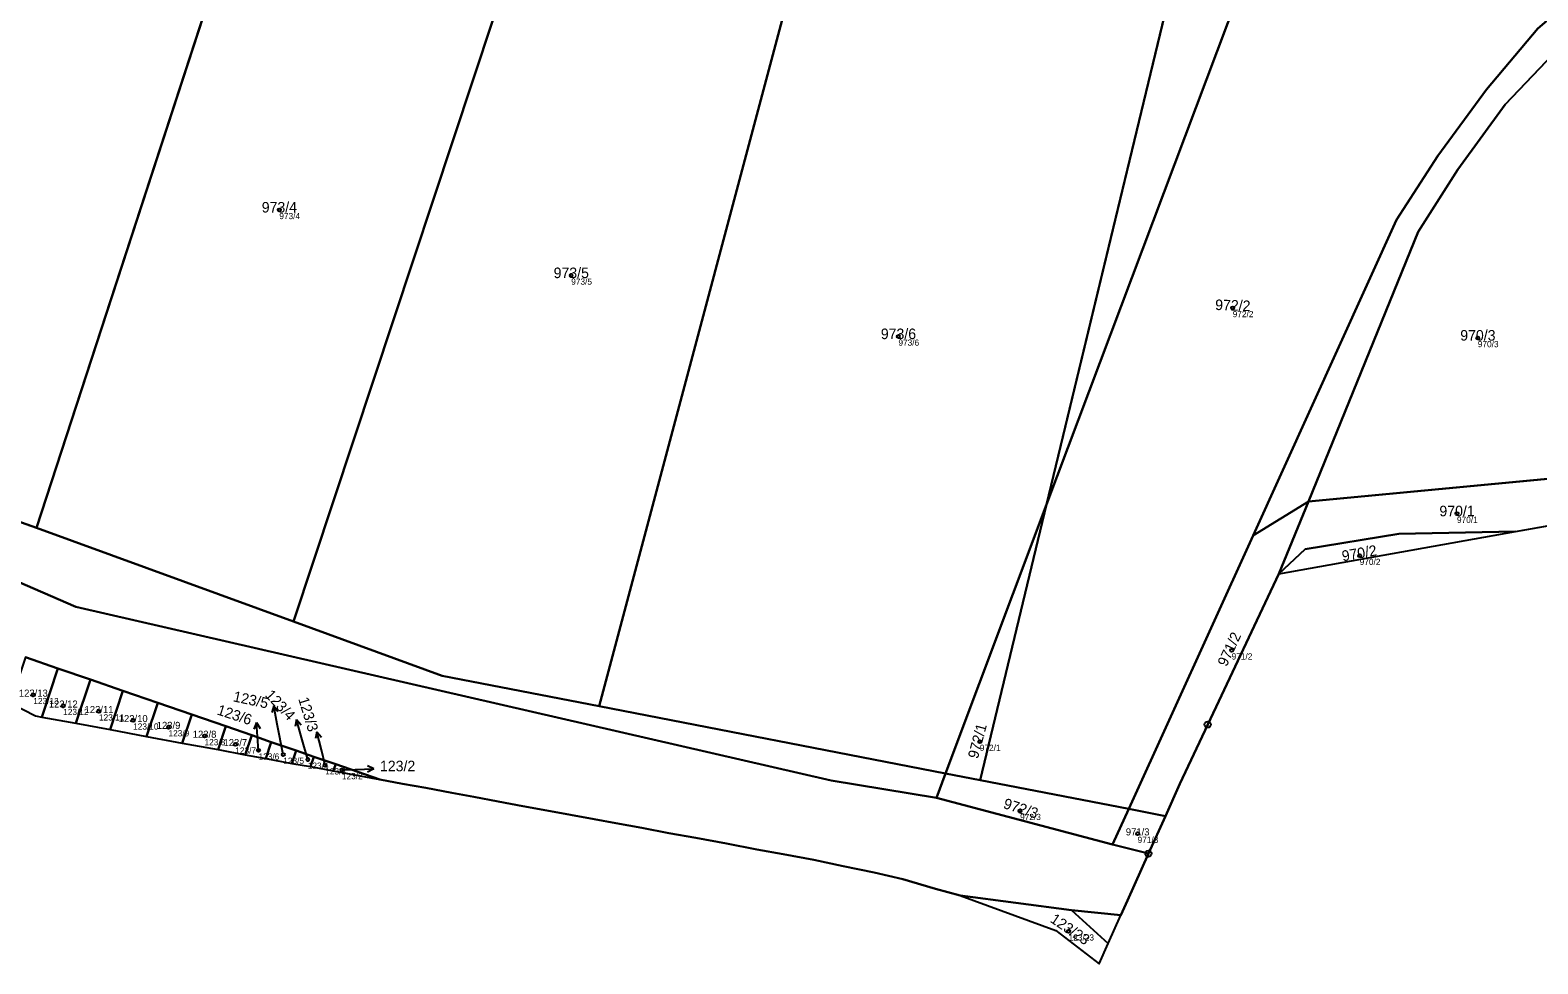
# Model space of a CAD drawing. Extents: x -603967 to -594699, y -1179315 to -1165625.
# Drawn here: x -597028 to -596784.9, y -1173029 to -1172878.5 of the extents above; entities that cross this region are included whole.
import ezdxf

# ---------------------------------------------------------------- set-up
doc = ezdxf.new("R2010")
doc.units = 0
for name, color, linetype in [('Definiční body', 7, 'Continuous'), ('Hranice parcel', 7, 'Continuous'), ('Parcelní čísla', 7, 'Continuous'), ('Polygon ku', 7, 'Continuous'), ('Polygon parcely', 7, 'Continuous'), ('Pop  PČ popisy', 7, 'Continuous'), ('Vnitřní kresba', 7, 'Continuous'), ('Značky bodu BP', 7, 'Continuous')]:
    doc.layers.add(name, color=color, linetype=linetype)

msp = doc.modelspace()

# ---------------------------------------------------------------- linework, layer by layer
at = {"layer": 'Definiční body'}
for centre in [(-596987.8, -1172907.46994), (-596940.73, -1172918.03994), (-596834.07, -1172923.26994), (-596887.97, -1172927.86994), (-596794.54, -1172928.10994), (-596797.9, -1172956.42994), (-596813.59, -1172963.20994), (-596834.24, -1172978.44994), (-597027.47, -1172985.63994), (-597022.65, -1172987.39994), (-597016.88, -1172988.27994), (-597011.37, -1172989.74994), (-597005.67, -1172990.83994), (-596999.86, -1172992.26994), (-596994.9, -1172993.61994), (-596874.84, -1172993.17994), (-596991.15, -1172994.58994), (-596987.16, -1172995.25994), (-596983.21, -1172996.05994), (-596980.4, -1172996.97994), (-596977.7, -1172997.73994), (-596868.35, -1173004.32994), (-596849.4, -1173008.00994), (-596860.52, -1173023.74994)]:
    msp.add_circle(centre, 0.25, dxfattribs=at)
at = {"layer": 'Hranice parcel'}
for p, q in [((-596822.8, -1172845.29), (-596864.07, -1172954.95)), ((-597026.93, -1172958.74), (-596990.34, -1172846.48)), ((-596985.54, -1172973.81), (-596943.64, -1172847.49)), ((-596936.25, -1172987.46), (-596898.99, -1172847.77)), ((-596864.07, -1172954.95), (-596837.74, -1172845.87)), ((-597073.38, -1172942.23), (-597026.93, -1172958.74)), ((-597075.1, -1172947.81), (-597020.63, -1172971.43)), ((-596770.73, -1172949.64), (-596821.84, -1172954.45)), ((-596830.78, -1172959.97), (-596821.84, -1172954.45)), ((-596821.84, -1172954.45), (-596826.61, -1172966.14)), ((-596864.07, -1172954.95), (-596880.38, -1172998.29)), ((-596874.79, -1172999.37), (-596864.07, -1172954.95)), ((-596788.47, -1172959.3), (-596769.76, -1172956)), ((-597026.93, -1172958.74), (-596985.54, -1172973.81)), ((-596826.61, -1172966.14), (-596788.47, -1172959.3)), ((-596830.78, -1172959.97), (-596850.82, -1173004.02)), ((-596826.61, -1172966.14), (-596838.09, -1172990.42)), ((-597028.74, -1172979.56), (-597023.49, -1172981.37)), ((-597023.49, -1172981.37), (-597026.09, -1172989.23)), ((-597023.49, -1172981.37), (-597018.25, -1172983.18)), ((-597018.25, -1172983.18), (-597020.6, -1172990.18)), ((-597018.25, -1172983.18), (-597013.02, -1172984.99)), ((-597013.02, -1172984.99), (-597015.06, -1172991.24)), ((-597013.02, -1172984.99), (-597007.4, -1172986.93)), ((-597007.4, -1172986.93), (-597009.2, -1172992.34)), ((-597007.4, -1172986.93), (-597001.92, -1172988.82)), ((-597001.92, -1172988.82), (-597003.44, -1172993.41)), ((-597001.92, -1172988.82), (-596996.45, -1172990.7)), ((-596936.25, -1172987.46), (-596880.38, -1172998.29)), ((-597026.09, -1172989.23), (-597020.6, -1172990.18)), ((-597020.6, -1172990.18), (-597015.06, -1172991.24)), ((-597015.06, -1172991.24), (-597009.2, -1172992.34)), ((-596996.45, -1172990.7), (-596997.67, -1172994.45)), ((-596996.45, -1172990.7), (-596992.25, -1172992.15)), ((-596838.09, -1172990.42), (-596842.61, -1173000)), ((-597009.2, -1172992.34), (-597003.44, -1172993.41)), ((-597003.44, -1172993.41), (-596997.67, -1172994.45)), ((-596992.25, -1172992.15), (-596993.31, -1172995.28)), ((-596992.25, -1172992.15), (-596989.1, -1172993.24)), ((-596989.1, -1172993.24), (-596990, -1172995.9)), ((-596989.1, -1172993.24), (-596985.08, -1172994.62)), ((-596997.67, -1172994.45), (-596993.31, -1172995.28)), ((-596993.31, -1172995.28), (-596990, -1172995.9)), ((-596990, -1172995.9), (-596985.77, -1172996.68)), ((-596985.08, -1172994.62), (-596985.77, -1172996.68)), ((-596985.08, -1172994.62), (-596982.23, -1172995.61)), ((-596982.23, -1172995.61), (-596982.77, -1172997.21)), ((-596982.23, -1172995.61), (-596978.71, -1172996.82)), ((-596985.77, -1172996.68), (-596982.77, -1172997.21)), ((-596982.77, -1172997.21), (-596979.1, -1172997.9)), ((-596978.71, -1172996.82), (-596979.1, -1172997.9)), ((-596979.1, -1172997.9), (-596971.59, -1172999.28)), ((-596978.71, -1172996.82), (-596971.59, -1172999.28)), ((-596880.38, -1172998.29), (-596881.85, -1173002.21)), ((-596880.38, -1172998.29), (-596874.79, -1172999.37)), ((-596967.93, -1172999.96), (-596971.59, -1172999.28)), ((-596964.19, -1173000.64), (-596967.93, -1172999.96)), ((-596959.97, -1173001.43), (-596964.19, -1173000.64)), ((-596874.79, -1172999.37), (-596850.82, -1173004.02)), ((-596842.61, -1173000), (-596844.91, -1173005.17)), ((-596956.44, -1173002.09), (-596959.97, -1173001.43)), ((-596952.52, -1173002.81), (-596956.44, -1173002.09)), ((-596948.52, -1173003.55), (-596952.52, -1173002.81)), ((-596881.85, -1173002.21), (-596853.43, -1173009.77)), ((-596944.65, -1173004.27), (-596948.52, -1173003.55)), ((-596940.84, -1173004.97), (-596944.65, -1173004.27)), ((-596937.01, -1173005.68), (-596940.84, -1173004.97)), ((-596933.51, -1173006.33), (-596937.01, -1173005.68)), ((-596850.82, -1173004.02), (-596853.43, -1173009.77)), ((-596850.82, -1173004.02), (-596844.91, -1173005.17)), ((-596844.91, -1173005.17), (-596847.65, -1173011.23)), ((-596929.34, -1173007.09), (-596933.51, -1173006.33)), ((-596924.98, -1173007.91), (-596929.34, -1173007.09)), ((-596920.63, -1173008.7), (-596924.98, -1173007.91)), ((-596915.7, -1173009.6), (-596920.63, -1173008.7)), ((-596910.8, -1173010.54), (-596915.7, -1173009.6)), ((-596906.56, -1173011.3), (-596910.8, -1173010.54)), ((-596853.43, -1173009.77), (-596847.65, -1173011.23)), ((-596901.61, -1173012.25), (-596906.56, -1173011.3)), ((-596896.86, -1173013.25), (-596901.61, -1173012.25)), ((-596891.86, -1173014.28), (-596896.86, -1173013.25)), ((-596887.26, -1173015.33), (-596891.86, -1173014.28)), ((-596881.97, -1173016.88), (-596887.26, -1173015.33)), ((-596878.01, -1173017.99), (-596881.97, -1173016.88)), ((-596878.01, -1173017.99), (-596862.6, -1173023.61)), ((-596862.6, -1173023.61), (-596855.6, -1173028.99))]:
    msp.add_line(p, q, dxfattribs=at)
for points in [[(-596748.76, -1172839.35), (-596749.31, -1172846.64), (-596755.77, -1172857.84), (-596763.88, -1172864.57), (-596772.39, -1172868.75), (-596779.67, -1172873.77), (-596784.84, -1172878.21), (-596793.12, -1172888.04), (-596800.99, -1172898.76), (-596807.63, -1172909.06), (-596830.78, -1172959.97)], [(-596781.25, -1172881.18), (-596790.11, -1172890.5), (-596797.77, -1172900.95), (-596804.18, -1172910.98), (-596821.84, -1172954.45)], [(-596826.61, -1172966.14), (-596822.38, -1172962.16), (-596807.27, -1172959.66), (-596788.47, -1172959.3)], [(-597020.63, -1172971.43), (-596898.81, -1172999.45), (-596881.85, -1173002.21)], [(-596985.54, -1172973.81), (-596961.56, -1172982.55), (-596936.25, -1172987.46)], [(-597031.2, -1172986.91), (-597027.13, -1172988.99), (-597026.09, -1172989.23)], [(-596847.65, -1173011.23), (-596851.03, -1173018.78), (-596852.09, -1173021.17)], [(-596852.09, -1173021.17), (-596860.07, -1173020.33), (-596878.01, -1173017.99)], [(-596855.6, -1173028.99), (-596854.12, -1173025.71), (-596852.09, -1173021.17)]]:
    msp.add_lwpolyline(points, dxfattribs=at)
at = {"layer": 'Polygon ku'}
msp.add_lwpolyline([(-597031.2, -1172986.91), (-597027.13, -1172988.99), (-597026.09, -1172989.23), (-597020.6, -1172990.18), (-597015.06, -1172991.24), (-597009.2, -1172992.34), (-597003.44, -1172993.41), (-596997.67, -1172994.45), (-596993.31, -1172995.28), (-596990, -1172995.9), (-596985.77, -1172996.68), (-596982.77, -1172997.21), (-596979.1, -1172997.9), (-596971.59, -1172999.28), (-596967.93, -1172999.96), (-596964.19, -1173000.64), (-596959.97, -1173001.43), (-596956.44, -1173002.09), (-596952.52, -1173002.81), (-596948.52, -1173003.55), (-596944.65, -1173004.27), (-596940.84, -1173004.97), (-596937.01, -1173005.68), (-596933.51, -1173006.33), (-596929.34, -1173007.09), (-596924.98, -1173007.91), (-596920.63, -1173008.7), (-596915.7, -1173009.6), (-596910.8, -1173010.54), (-596906.56, -1173011.3), (-596901.61, -1173012.25), (-596896.86, -1173013.25), (-596891.86, -1173014.28), (-596887.26, -1173015.33), (-596881.97, -1173016.88), (-596878.01, -1173017.99), (-596862.6, -1173023.61), (-596855.6, -1173028.99), (-596854.12, -1173025.71), (-596852.09, -1173021.17), (-596851.03, -1173018.78), (-596847.65, -1173011.23), (-596844.91, -1173005.17), (-596842.61, -1173000), (-596838.09, -1172990.42), (-596826.61, -1172966.14), (-596788.47, -1172959.3), (-596769.76, -1172956)], dxfattribs=at)
at = {"layer": 'Polygon parcely'}
for points in [[(-596784.84, -1172878.21), (-596793.12, -1172888.04), (-596800.99, -1172898.76), (-596807.63, -1172909.06), (-596830.78, -1172959.97), (-596821.84, -1172954.45), (-596804.18, -1172910.98), (-596797.77, -1172900.95), (-596790.11, -1172890.5), (-596781.25, -1172881.18), (-596776.38, -1172876.94), (-596770.13, -1172873.12), (-596762.46, -1172870.6), (-596752.18, -1172869.36), (-596749.45, -1172866.51), (-596739.86, -1172838.12), (-596743.8, -1172838.67), (-596747.11, -1172839.12), (-596748.76, -1172839.35), (-596749.31, -1172846.64), (-596755.77, -1172857.84), (-596763.88, -1172864.57), (-596772.39, -1172868.75), (-596779.67, -1172873.77)], [(-596864.07, -1172954.95), (-596874.79, -1172999.37), (-596850.82, -1173004.02), (-596830.78, -1172959.97), (-596807.63, -1172909.06), (-596800.99, -1172898.76), (-596793.12, -1172888.04), (-596784.84, -1172878.21), (-596779.67, -1172873.77), (-596772.39, -1172868.75), (-596763.88, -1172864.57), (-596755.77, -1172857.84), (-596749.31, -1172846.64), (-596748.76, -1172839.35), (-596761.98, -1172839.62), (-596770.71, -1172839.61), (-596781.48, -1172840.52), (-596791.83, -1172841.5), (-596822.8, -1172845.29)], [(-596822.8, -1172845.29), (-596837.74, -1172845.87), (-596864.07, -1172954.95)], [(-597026.93, -1172958.74), (-596990.34, -1172846.48), (-597014.79, -1172845.99), (-597021.38, -1172845.6), (-597028.12, -1172847.57), (-597034.3, -1172850.24), (-597040.39, -1172854.43), (-597045.25, -1172860.28), (-597049.04, -1172866.95), (-597052.36, -1172873.78), (-597073.38, -1172942.23)], [(-596985.54, -1172973.81), (-596943.64, -1172847.49), (-596944.87, -1172847.4), (-596990.34, -1172846.48), (-597026.93, -1172958.74)], [(-596961.56, -1172982.55), (-596936.25, -1172987.46), (-596898.99, -1172847.77), (-596900.96, -1172847.77), (-596926.4, -1172848.75), (-596943.64, -1172847.49), (-596985.54, -1172973.81)], [(-596880.38, -1172998.29), (-596864.07, -1172954.95), (-596837.74, -1172845.87), (-596841.19, -1172846.01), (-596888.63, -1172847.79), (-596898.99, -1172847.77), (-596936.25, -1172987.46)], [(-596797.77, -1172900.95), (-596804.18, -1172910.98), (-596821.84, -1172954.45), (-596770.73, -1172949.64), (-596781.25, -1172881.18), (-596790.11, -1172890.5)], [(-596898.81, -1172999.45), (-596881.85, -1173002.21), (-596880.38, -1172998.29), (-596936.25, -1172987.46), (-596961.56, -1172982.55), (-596985.54, -1172973.81), (-597026.93, -1172958.74), (-597073.38, -1172942.23), (-597075.1, -1172947.81), (-597020.63, -1172971.43)], [(-596826.61, -1172966.14), (-596822.38, -1172962.16), (-596807.27, -1172959.66), (-596788.47, -1172959.3), (-596769.76, -1172956), (-596770.73, -1172949.64), (-596821.84, -1172954.45)], [(-596844.91, -1173005.17), (-596842.61, -1173000), (-596838.09, -1172990.42), (-596826.61, -1172966.14), (-596821.84, -1172954.45), (-596830.78, -1172959.97), (-596850.82, -1173004.02)], [(-596874.79, -1172999.37), (-596864.07, -1172954.95), (-596880.38, -1172998.29)], [(-596788.47, -1172959.3), (-596807.27, -1172959.66), (-596822.38, -1172962.16), (-596826.61, -1172966.14)], [(-597031.2, -1172986.91), (-597027.13, -1172988.99), (-597026.09, -1172989.23), (-597023.49, -1172981.37), (-597028.74, -1172979.56)], [(-597026.09, -1172989.23), (-597020.6, -1172990.18), (-597018.25, -1172983.18), (-597023.49, -1172981.37)], [(-597020.6, -1172990.18), (-597015.06, -1172991.24), (-597013.02, -1172984.99), (-597018.25, -1172983.18)], [(-597015.06, -1172991.24), (-597009.2, -1172992.34), (-597007.4, -1172986.93), (-597013.02, -1172984.99)], [(-597007.4, -1172986.93), (-597009.2, -1172992.34), (-597003.44, -1172993.41), (-597001.92, -1172988.82)], [(-597003.44, -1172993.41), (-596997.67, -1172994.45), (-596996.45, -1172990.7), (-597001.92, -1172988.82)], [(-596997.67, -1172994.45), (-596993.31, -1172995.28), (-596992.25, -1172992.15), (-596996.45, -1172990.7)], [(-596993.31, -1172995.28), (-596990, -1172995.9), (-596989.1, -1172993.24), (-596992.25, -1172992.15)], [(-596990, -1172995.9), (-596985.77, -1172996.68), (-596985.08, -1172994.62), (-596989.1, -1172993.24)], [(-596985.77, -1172996.68), (-596982.77, -1172997.21), (-596982.23, -1172995.61), (-596985.08, -1172994.62)], [(-596982.77, -1172997.21), (-596979.1, -1172997.9), (-596978.71, -1172996.82), (-596982.23, -1172995.61)], [(-596979.1, -1172997.9), (-596971.59, -1172999.28), (-596978.71, -1172996.82)], [(-596853.43, -1173009.77), (-596850.82, -1173004.02), (-596874.79, -1172999.37), (-596880.38, -1172998.29), (-596881.85, -1173002.21)], [(-596847.65, -1173011.23), (-596844.91, -1173005.17), (-596850.82, -1173004.02), (-596853.43, -1173009.77)], [(-596852.09, -1173021.17), (-596860.07, -1173020.33), (-596878.01, -1173017.99), (-596862.6, -1173023.61), (-596855.6, -1173028.99), (-596854.12, -1173025.71)]]:
    msp.add_lwpolyline(points, close=True, dxfattribs=at)
msp.add_lwpolyline([(-597028.74, -1172979.56), (-597023.49, -1172981.37), (-597018.25, -1172983.18), (-597013.02, -1172984.99), (-597007.4, -1172986.93), (-597001.92, -1172988.82), (-596996.45, -1172990.7), (-596992.25, -1172992.15), (-596989.1, -1172993.24), (-596985.08, -1172994.62), (-596982.23, -1172995.61), (-596978.71, -1172996.82), (-596971.59, -1172999.28), (-596967.93, -1172999.96), (-596964.19, -1173000.64), (-596959.97, -1173001.43), (-596956.44, -1173002.09), (-596952.52, -1173002.81), (-596948.52, -1173003.55), (-596944.65, -1173004.27), (-596940.84, -1173004.97), (-596937.01, -1173005.68), (-596933.51, -1173006.33), (-596929.34, -1173007.09), (-596924.98, -1173007.91), (-596920.63, -1173008.7), (-596915.7, -1173009.6), (-596910.8, -1173010.54), (-596906.56, -1173011.3), (-596901.61, -1173012.25), (-596896.86, -1173013.25), (-596891.86, -1173014.28), (-596887.26, -1173015.33), (-596881.97, -1173016.88), (-596878.01, -1173017.99), (-596860.07, -1173020.33), (-596852.09, -1173021.17), (-596851.03, -1173018.78), (-596847.65, -1173011.23), (-596853.43, -1173009.77), (-596881.85, -1173002.21), (-596898.81, -1172999.45), (-597020.63, -1172971.43), (-597075.1, -1172947.81)], dxfattribs=at)
at = {"layer": 'Pop  PČ popisy'}
for p, q in [((-596988.703, -1172987.424), (-596989.003, -1172988.503)), ((-596988.13, -1172990.37), (-596988.703, -1172987.424)), ((-596988.703, -1172987.424), (-596988.02, -1172988.312)), ((-596991.459, -1172990.116), (-596991.889, -1172991.15)), ((-596991.25, -1172993.11), (-596991.459, -1172990.116)), ((-596991.459, -1172990.116), (-596990.89, -1172991.08)), ((-596987.16, -1172995.26), (-596988.13, -1172990.37)), ((-596985.037, -1172989.625), (-596985.242, -1172990.726)), ((-596984.21, -1172992.51), (-596985.037, -1172989.625)), ((-596985.037, -1172989.625), (-596984.28, -1172990.45)), ((-596991.15, -1172994.59), (-596991.25, -1172993.11)), ((-596983.21, -1172996.06), (-596984.21, -1172992.51)), ((-596981.726, -1172991.598), (-596981.97, -1172992.691)), ((-596981, -1172994.51), (-596981.726, -1172991.598)), ((-596981.726, -1172991.598), (-596980.998, -1172992.449)), ((-596980.4, -1172996.98), (-596981, -1172994.51)), ((-596977.7, -1172997.74), (-596975.57, -1172997.65)), ((-596975.57, -1172997.65), (-596972.571, -1172997.545)), ((-596972.571, -1172997.545), (-596973.589, -1172997.08)), ((-596972.571, -1172997.545), (-596973.554, -1172998.081))]:
    msp.add_line(p, q, dxfattribs=at)
at = {"layer": 'Vnitřní kresba'}
msp.add_line((-596860.07, -1173020.33), (-596854.12, -1173025.71), dxfattribs=at)
at = {"layer": 'Značky bodu BP'}
for centre, radius in [((-596838.09, -1172990.41988), 0.5), ((-596838.09, -1172990.41988), 0.0303), ((-596847.65, -1173011.22988), 0.5), ((-596847.65, -1173011.22988), 0.0303)]:
    msp.add_circle(centre, radius, dxfattribs=at)

# ---------------------------------------------------------------- texts
at = {"layer": 'Definiční body'}
for s, p in [('973/4', (-596987.8, -1172908.959)), ('973/5', (-596940.73, -1172919.529)), ('972/2', (-596834.07, -1172924.759)), ('973/6', (-596887.97, -1172929.359)), ('970/3', (-596794.54, -1172929.599)), ('970/1', (-596797.9, -1172957.919)), ('970/2', (-596813.59, -1172964.699)), ('971/2', (-596834.24, -1172979.939)), ('123/13', (-597027.47, -1172987.129)), ('123/12', (-597022.65, -1172988.889)), ('123/11', (-597016.88, -1172989.769)), ('123/10', (-597011.37, -1172991.239)), ('123/9', (-597005.67, -1172992.329)), ('123/8', (-596999.86, -1172993.759)), ('972/1', (-596874.84, -1172994.669)), ('123/7', (-596994.9, -1172995.109)), ('123/6', (-596991.15, -1172996.079)), ('123/5', (-596987.16, -1172996.749)), ('123/4', (-596983.21, -1172997.549)), ('123/3', (-596980.4, -1172998.469)), ('123/2', (-596977.7, -1172999.229)), ('972/3', (-596868.35, -1173005.819)), ('971/3', (-596849.4, -1173009.499)), ('123/23', (-596860.52, -1173025.239))]:
    msp.add_text(s, height=0.999996, dxfattribs=at).set_placement(p)
at = {"layer": 'Parcelní čísla'}
for s, height, p in [('973/4', 1.699998, (-596990.636, -1172907.895)), ('973/5', 1.699998, (-596943.566, -1172918.465)), ('973/6', 1.699998, (-596890.806, -1172928.295)), ('970/3', 1.699998, (-596797.376, -1172928.535)), ('970/1', 1.699998, (-596800.736, -1172956.855)), ('123/13', 1.14, (-597029.794, -1172985.925)), ('123/12', 1.14, (-597024.974, -1172987.685)), ('123/11', 1.14, (-597019.204, -1172988.565)), ('123/10', 1.14, (-597013.694, -1172990.035)), ('123/9', 1.14, (-597007.571, -1172991.125)), ('123/8', 1.14, (-597001.761, -1172992.555)), ('123/7', 1.14, (-596996.801, -1172993.905)), ('123/2', 1.699998, (-596971.57, -1172997.955)), ('971/3', 1.14, (-596851.301, -1173008.295))]:
    msp.add_text(s, height=height, dxfattribs=at).set_placement(p)
for s, rotation, p in [('972/2', 358, (-596836.919, -1172923.595)), ('970/2', 10, (-596816.309, -1172964.121)), ('971/2', 65, (-596835.053, -1172981.199)), ('123/5', 348, (-596995.346, -1172986.666)), ('123/4', 313, (-596990.199, -1172985.761)), ('123/3', 287, (-596984.764, -1172986.289)), ('123/6', 342, (-596997.975, -1172988.771)), ('972/1', 75, (-596875.163, -1172996.029)), ('972/3', 342, (-596871.178, -1173003.857)), ('123/23', 326, (-596863.631, -1173022.163))]:
    msp.add_text(s, height=1.699998, rotation=rotation, dxfattribs=at).set_placement(p)

doc.saveas('drawing.dxf')
